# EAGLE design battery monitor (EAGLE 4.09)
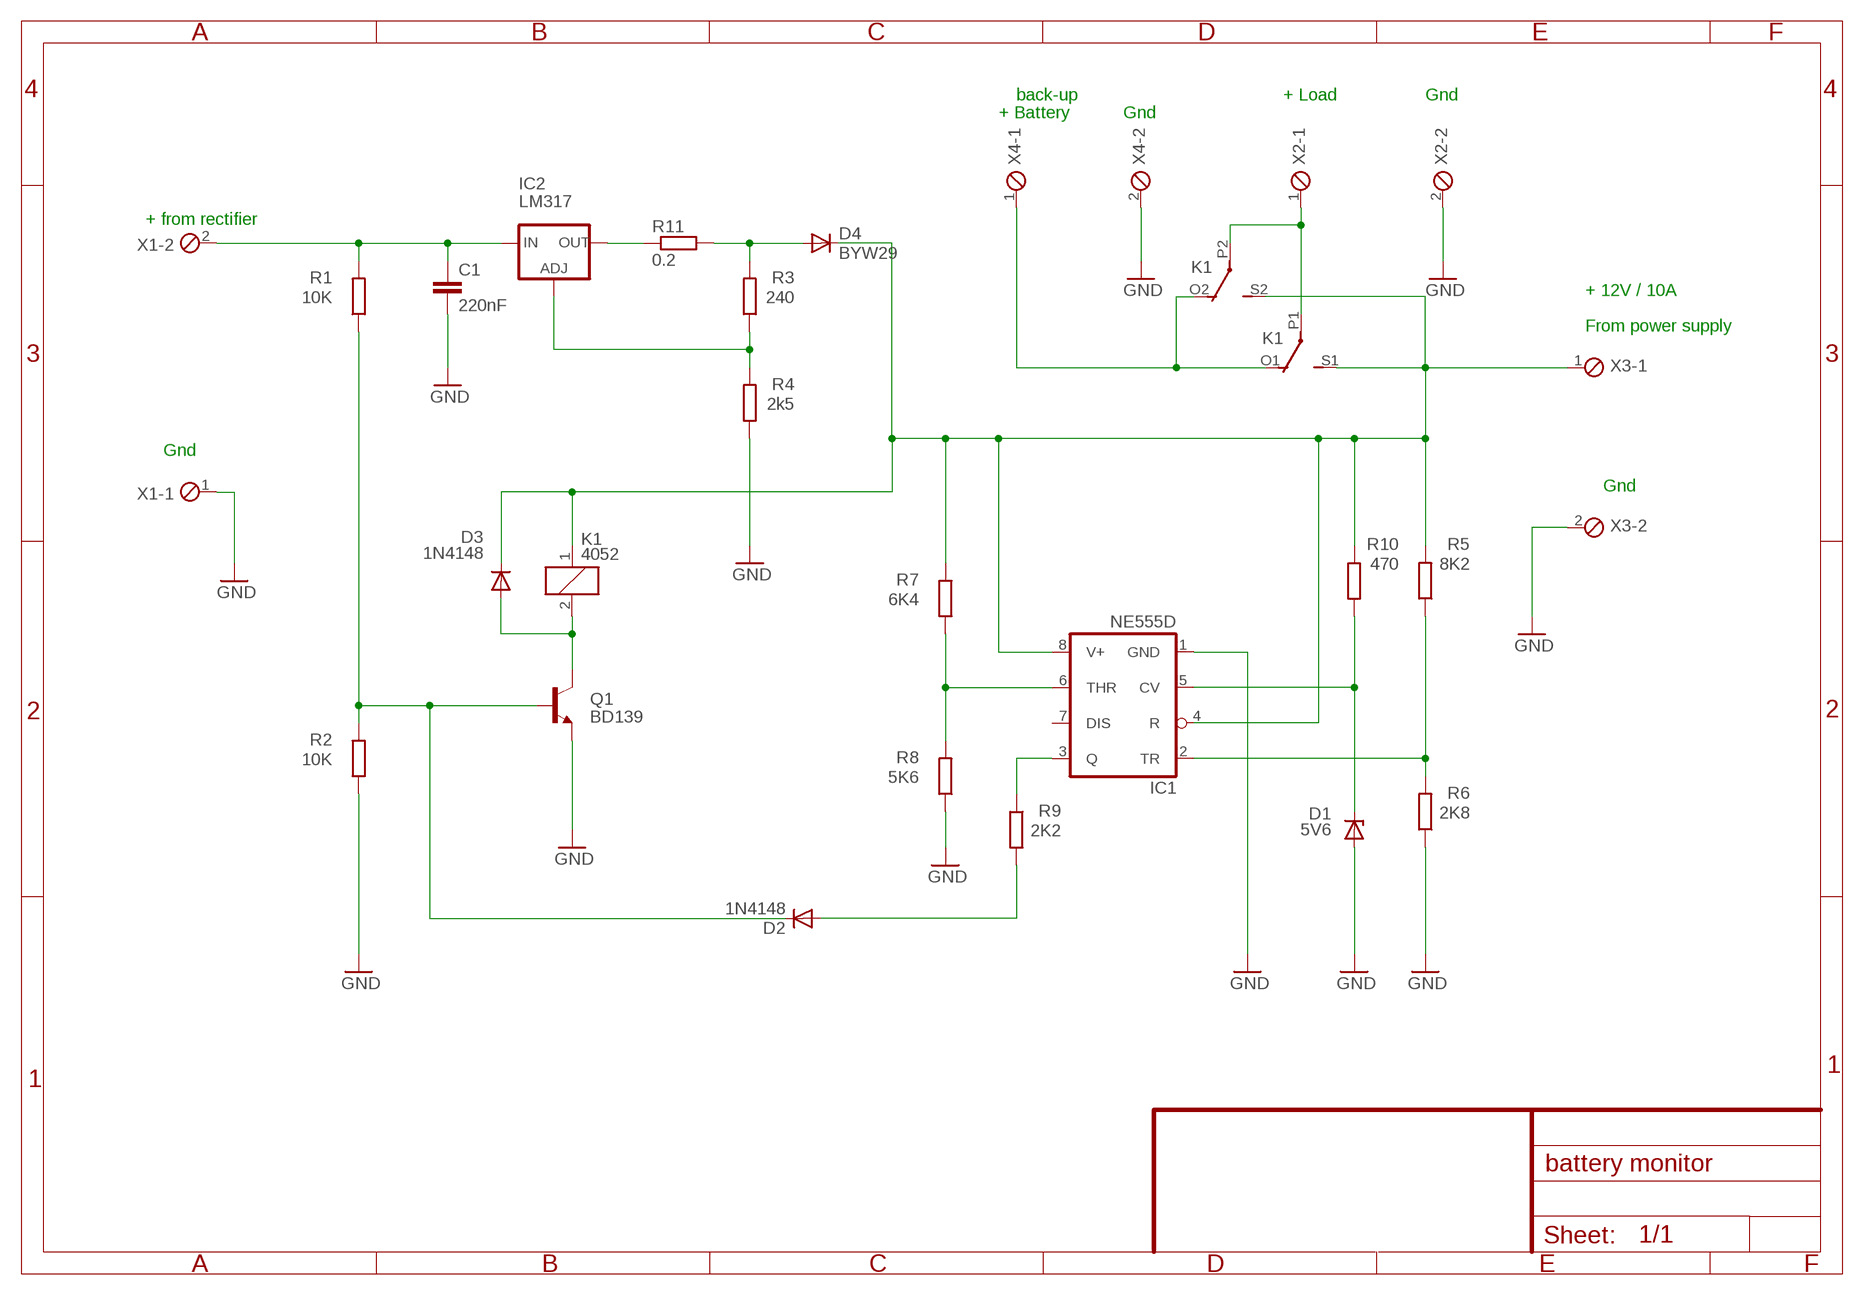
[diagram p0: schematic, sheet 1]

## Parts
C1  220nF  C-EU025_050-035X075  [C025_050-035X075]
D1  5V6  ZENER-DIODESMB  [SMB]
D2  1N4148  DIODE-SMB  [SMB]
D3  1N4148  DIODE-SMB  [SMB]
D4  BYW29  [DO220S]
IC1  NE555D  [SO08]
IC2  LM317  LM317TS  [317TS]
K1  4052  [F4052]
Q1  BD139  [TO126]
R1  10K  R-EU_M1206  [M1206]
R2  10K  R-EU_M1206  [M1206]
R3  240  R-EU_M1206  [M1206]
R4  2k5  R-EU_M1206  [M1206]
R5  8K2  R-EU_M1206  [M1206]
R6  2K8  R-EU_M1206  [M1206]
R7  6K4  R-EU_M1206  [M1206]
R8  5K6  R-EU_M1206  [M1206]
R9  2K2  R-EU_M1206  [M1206]
R10  470  R-EU_M1206  [M1206]
R11  0.2  R-EU_0922/22  [0922/22]
X1  MPT2  [2POL254]
X2  MPT2  [2POL254]
X3  MPT2  [2POL254]
X4  MPT2  [2POL254]

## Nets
GND: C1.2 D1.A IC1.1(GND) Q1.1(E) R2.1 R4.1 R6.1 R8.1 X1.1 X2.2 X3.2 X4.2
N$1: IC1.6(THR) R7.1 R8.2
N$2: IC1.2(TR) R5.1 R6.2
N$3: IC1.3(Q) R9.1
N$4: D2.A R9.2
N$5: D1.C IC1.5(CV) R10.2
N$6: C1.1 IC2.3(IN) R1.2 X1.2
N$7: IC2.2(OUT) R11.1
N$8: D4.A R3.2 R11.2
N$9: IC2.1(ADJ) R3.1 R4.2
N$10: D3.A K1.2 Q1.2(C)
N$11: D2.C Q1.3(B) R1.1 R2.2
N$12: K1.P1(2:P) K1.P2(3:P) X2.1
N$13: D3.C D4.C IC1.4(R) IC1.8(V+) K1.1 K1.S1(2:S) K1.S2(3:S) R5.2 R7.2 R10.1 X3.1
N$14: K1.O1(2:O) K1.O2(3:O) X4.1
Unconnected: IC1.7(DIS)

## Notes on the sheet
- back-up | + Load | Gnd
- + Battery | Gnd
- + from rectifier
- + 12V / 10A
- From power supply
- Gnd
- Gnd

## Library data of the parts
C1 = rcl:C-EU: CAPACITOR, European symbol
D1 = diode:ZENER-DIODE: Z-Diode
D2 D3 = diode:DIODE-: DIODE
D4 = diode:BYW29: DIODE
IC1 = linear:*555: TIMER
IC2 = v-reg:LM317TS: VOLTAGE REGULATOR
K1 = relay:4052: RELAY 2 x switch, Finder
Q1 = transistor-npn:BD139*: NPN Transistor
R1-R11 = rcl:R-EU_: RESISTOR, European symbol
X1-X4 = con-phoenix-254:MPT2: PHOENIX CONNECTOR

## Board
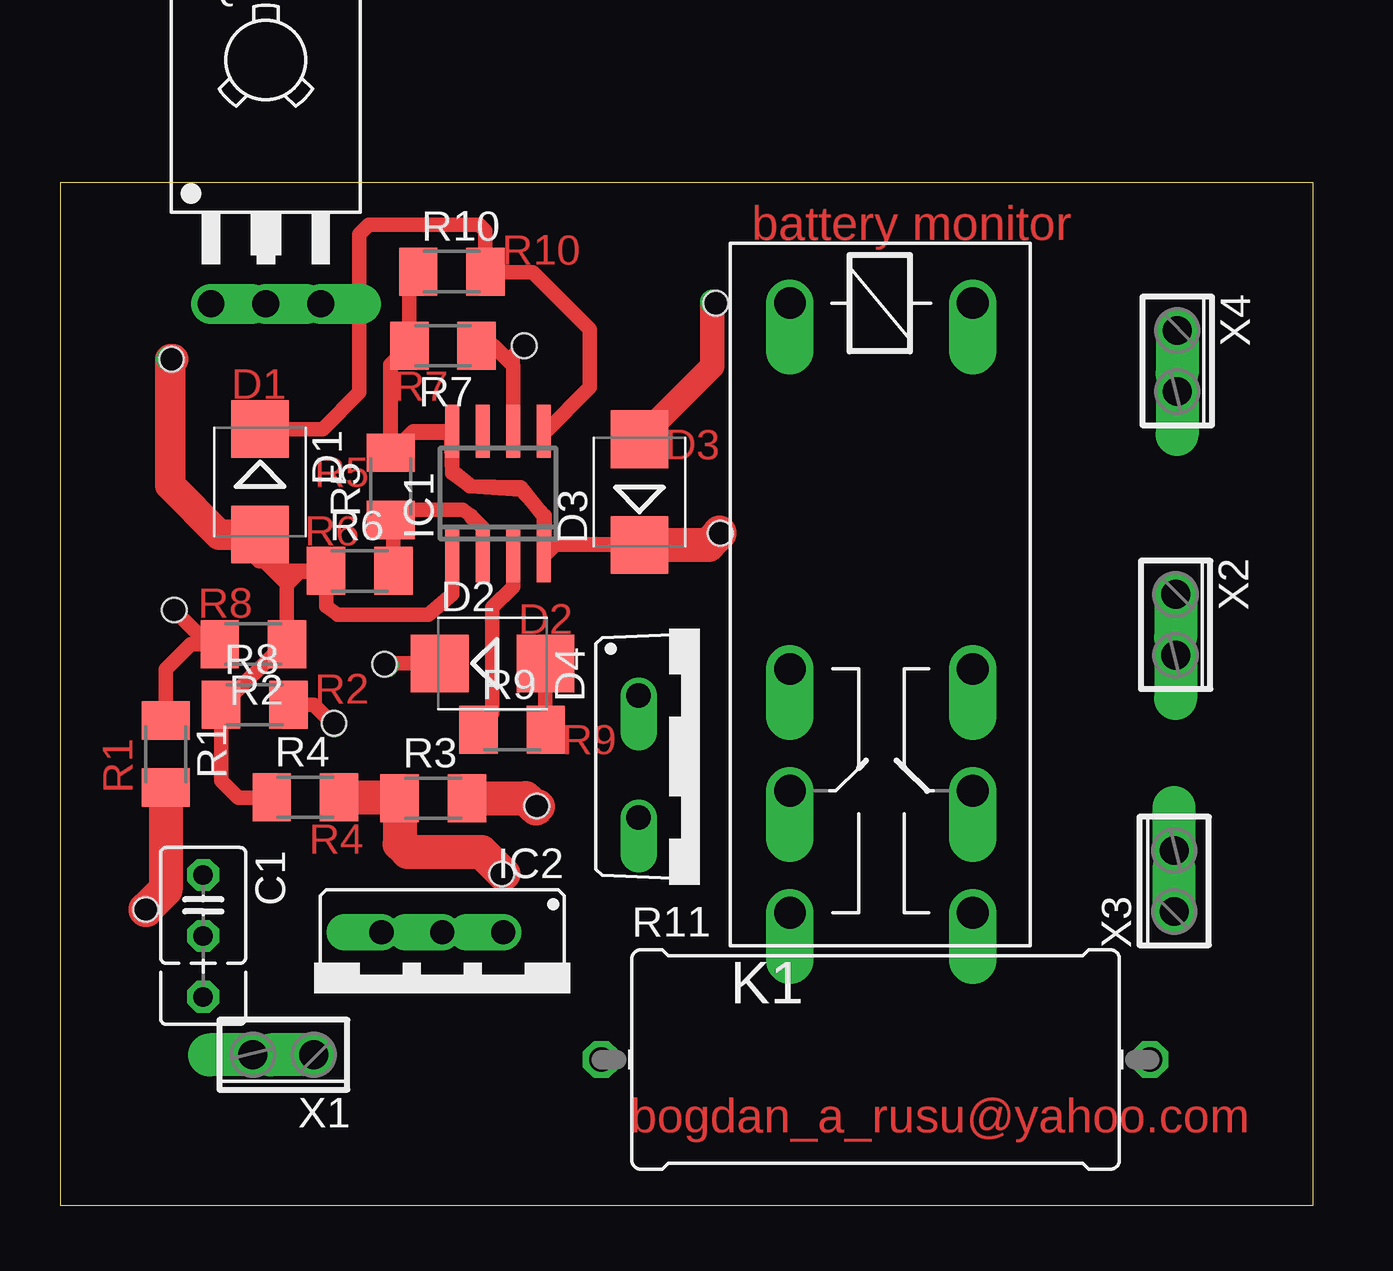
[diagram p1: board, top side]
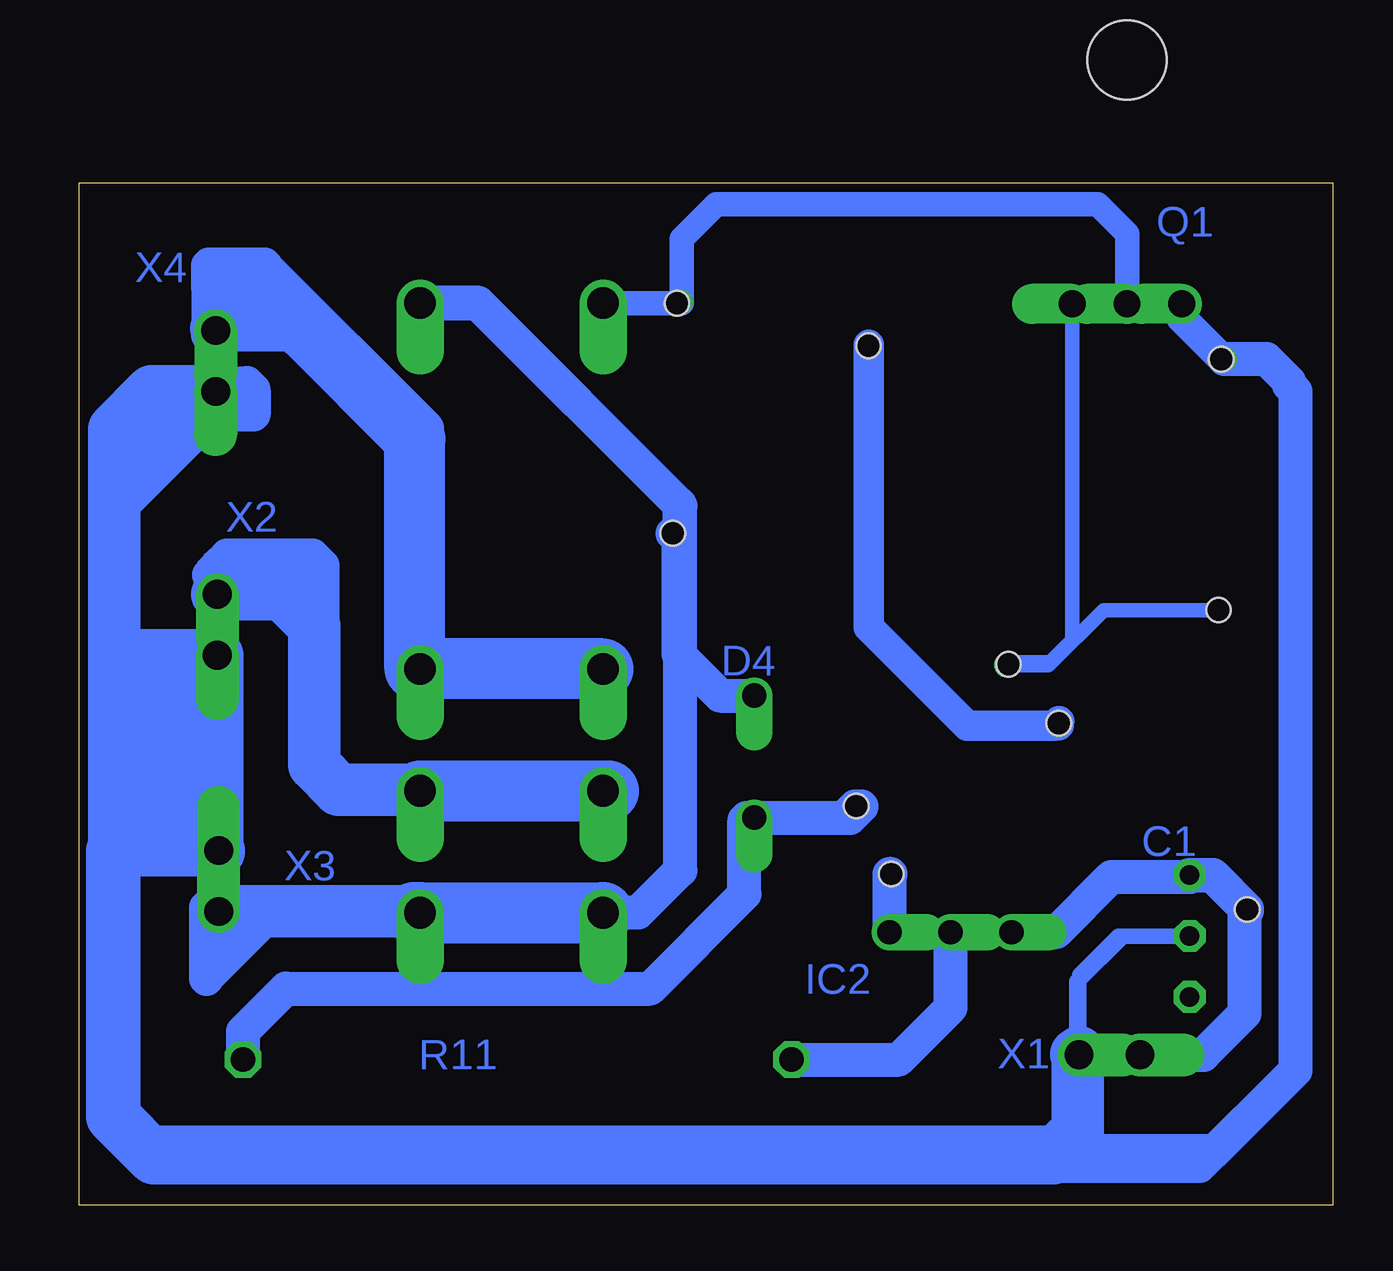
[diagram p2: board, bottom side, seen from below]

Size 52.23 x 42.62 mm. Coordinates in mm from the lower left corner, seen from the top.
Outline: 0,0 52.23,0 52.23,42.62 0,42.62 0,0
Copper layers used: Top, Bottom
Holes 1.02 mm at 19.86,16.64 18.4,13.8 3.57,12.33 27.51,28 27.33,37.59 4.65,35.25 13.52,22.55 4.76,24.81 19.35,35.82 11.42,20.09

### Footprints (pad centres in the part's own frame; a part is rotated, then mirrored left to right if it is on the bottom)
C025_050-035X075 = drill 0.813 octagon: 1 -1.27,0; 2 1.27,0; 3 3.81,0
SMB = smd 2.4 x 2.4: A 2.2,0; C -2.2,0
DO220S = drill 1.016 offset: A 2.54,-2.54; C -2.54,-2.54
SO08 = smd 0.6 x 2.2: 1 -1.905,-2.6; 2 -0.635,-2.6; 3 0.635,-2.6; 4 1.905,-2.6; 5 1.905,2.6; 6 0.635,2.6; 7 -0.635,2.6; 8 -1.905,2.6
317TS = drill 1.016 offset: 1 -2.54,-2.54; 2 0,-2.54; 3 2.54,-2.54
F4052 = drill 1.321 offset: 1 -3.81,3.81; 2 -3.81,-3.81; O1 11.43,-3.81; O2 11.43,3.81; P1 16.51,-3.81; P2 16.51,3.81; S1 21.59,-3.81; S2 21.59,3.81
TO126 = drill 1.118 offset: 1 -2.286,-5.08; 2 0,-5.08; 3 2.286,-5.08 | hole 3.302: 0,5.08
M1206 = smd 1.6 x 2: 1 -1.4,0; 2 1.4,0
0922/22 = drill 1.016 octagon: 1 -11.43,0; 2 11.43,0
2POL254 = drill 1.2 offset: 1 -1.27,0; 2 1.27,0

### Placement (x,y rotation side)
C1  5.97,12.5 270 top
D1  8.33,30.15 270 top
D2  18.02,22.58 0 top
D3  24.14,29.72 90 top
D4  26.65,18.7 270 top
IC1  18.25,29.66 0 top
IC2  15.93,8.84 180 top
K1  34.22,33.78 270 top
Q1  8.58,42.64 0 top
R1  4.4,18.8 270 top
R2  8.06,23.39 180 top
R3  15.55,16.96 0 top
R4  10.22,17.01 0 top
R5  13.78,29.96 90 top
R6  12.49,26.43 0 top
R7  15.96,35.82 180 top
R8  8.11,20.86 0 top
R9  18.84,19.81 0 top
R10  16.33,38.91 0 top
R11  33.98,6.08 0 top
X1  9.31,6.28 180 top
X2  46.48,24.19 270 top
X3  46.42,13.52 90 top
X4  46.55,35.18 270 top

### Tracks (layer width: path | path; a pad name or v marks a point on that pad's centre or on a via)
GND  (via drill 0.61)
  Top 0.406: R4.1 7.52,17.01 6.62,17.91 6.62,20.95 6.68,21.02 6.96,21.02 9.39,23.45 9.39,25.81 8.44,26.76 8.24,26.76 6.01,28.98 5.87,28.98 4.46,30.4 4.46,35.2 v4.52,35.26
  Top 0.61: R4.1 8.78,17.01 8.76,16.99 7.42,16.99 6.71,17.7 R8.1 6.79,20.86 9.31,23.39 R2.1 9.46,25.86 10,26.4 10.94,26.4 10.97,26.43 R6.1 | R6.1 9.12,26.43 8.32,27.24 8.32,27.89 8.27,27.93 8.28,27.95 D1.A | R6.1 11.09,26.4 11.04,26.35 11.09,26.3 11.09,24.96 11.58,24.62 15.35,24.62 16.35,25.47 16.35,25.49 16.34,25.5 16.35,25.51 IC1.1
  Top 1.27: D1.A 6.64,27.95 4.59,30 4.59,35.13 4.73,35.26 v4.59,35.26
  Bottom 0.61: 10.56,6.37 10.56,9.61 8.94,11.23 C1.2 5.97,11.24 | 10.7,6.31 10.7,9.34 8.84,11.2 | 5.97,11.24 5.95,11.26 | 8.84,11.2 6.01,11.2 5.97,11.24 | 8.74,11.2 8.71,11.23 | 8.74,11.2 8.84,11.2 | 10.67,2.92 10.67,9.27 8.74,11.2
  Bottom 1.27: Q1.1 6.29,36.97 v4.59,35.26
  Bottom 1.422: v4.52,35.26 2.77,35.26 1.82,34.32 1.82,34.18 1.55,33.91 1.55,5.62 4.93,2.24 9.99,2.24 10.67,2.92
  Bottom 2.184: X4.2 49.21,33.91 50.78,32.34 50.78,22.9 | 50.78,22.9 50.78,3.69 49.06,1.97 11.8,1.97 10.63,3.14 10.63,6.31 10.56,6.37 | 50.78,22.9 50.77,22.92 X2.2 46.48,14.75 46.45,14.71 46.42,14.73 X3.2 50.84,14.79 50.85,14.78 50.85,3.69 49.13,1.97 11.66,1.97 10.63,3 | 50.78,22.9 50.78,3.62 49.41,2.24 11.39,2.24 10.63,3 | X1.1 10.58,6.11 10.56,6.1 10.63,6.03 10.63,3 | 10.63,3 10.63,6.24 10.7,6.31
N$1  (via drill 0.61)
  Top 0.61: IC1.6 18.89,34.99 18.12,35.76 17.33,35.76 17.36,35.79 R7.1 18.08,35.82 18.87,35.03 18.87,35.39 v19.35,35.86 | R8.2 10.57,20.86 v11.42,20.01
  Bottom 1.27: v19.35,35.86 19.35,24.09 15.25,19.99 11.59,19.99 11.42,20.16 | 11.41,20.18 11.42,20.16 | 11.42,20.16 v11.42,20.01
N$2
  Top 0.61: IC1.2 17.62,28.24 17.23,28.63 17.18,28.63 17.13,28.68 17.13,28.73 16.78,28.97 13.81,28.97 13.78,28.74 R5.1 13.69,28.56 13.66,28.53 13.89,28.3 R6.2
N$3
  Top 0.61: IC1.3 18.89,25.78 18.02,24.91 18.02,20.51 17.33,19.81 | 17.28,19.76 17.33,19.81 | 17.33,19.81 R9.1
N$4
  Top 0.61: 20.22,19.54 20.24,19.56 R9.2 | D2.A 20.22,19.54 | 20.22,19.54 20.2,19.52
N$5
  Top 0.61: D1.C 10.94,32.35 12.47,33.88 12.47,40.47 12.87,40.86 17.47,40.86 17.72,40.61 17.72,38.93 17.67,38.88 | 17.67,38.88 17.7,38.91 R10.2 | 17.67,38.88 19.7,38.88 22.08,36.5 22.08,34.08 20.22,32.22 20.17,32.26 IC1.5
N$6  (via drill 0.61)
  Top 1.422: v3.57,12.35 4.4,13.18 R1.2 4.4,13.14 v3.57,12.31 v3.61,12.31
  Bottom 1.422: X1.2 5.4,6.27 3.67,8 3.67,12.24 v3.61,12.31 | C1.1 4.99,13.77 v3.57,12.35 | IC2.3 11.54,11.38 9.23,13.69 5.95,13.69 5.88,13.76 5.05,13.76 3.57,12.28 v3.57,12.31
N$7
  Bottom 1.422: R11.1 18.09,6.08 15.93,8.23 15.93,11.2 16.07,11.33 16.02,11.38 IC2.2
N$8  (via drill 0.61)
  Top 0.61: 19.95,16.54 19.92,16.58 | 19.92,16.58 v19.92,16.62 | R3.2 19.53,16.96 19.92,16.58
  Top 1.422: v19.92,16.62 19.83,16.53 19.4,16.96 R3.2 | v19.92,16.62
  Bottom 1.422: D4.A 20.37,16.16 v19.92,16.62 19.65,16.62 | R11.2 45.41,7.24 43.63,9.03 28.45,9.03 24.52,12.96 24.52,16.05 24.43,16.15 20.12,16.15 19.65,16.62 | 19.65,16.62
N$9  (via drill 0.61)
  Top 1.422: R4.2 14.08,17.01 14.12,16.96 R3.1 14.15,15.06 14.48,14.73 17.56,14.73 v18.47,13.81
  Bottom 1.422: v18.47,13.81 18.43,13.81 18.47,13.77 IC2.1
N$10  (via drill 0.61)
  Top 1.016: D3.A 27.18,34.96 v27.18,37.64
  Bottom 1.016: v27.18,37.64 27.23,37.59 K1.2 30.45,37.59 | Q1.2 8.58,40.48 9.8,41.7 25.69,41.7 27.13,40.27 27.13,37.59 30.45,37.59 | 30.5,37.64 30.45,37.59
N$11  (via drill 0.61)
  Top 0.61: R1.1 4.4,22.34 5.44,23.38 6.48,23.38 6.63,23.23 6.66,23.26 R2.2 6.18,23.39 v4.76,24.81 | 13.48,22.51 13.55,22.58 D2.C 13.47,22.58 13.44,22.55 13.48,22.51 | 13.48,22.51 v13.6,22.51
  Bottom 0.61: v4.76,24.81 9.56,24.81 11.86,22.51 v13.6,22.51 | v13.6,22.51 13.64,22.51 | Q1.3 10.87,23.54 11.78,22.63 13.48,22.63 v13.6,22.51
N$12
  Bottom 2.184: X2.1 43.76,25.46 42.45,24.14 42.45,18.36 41.42,17.33 30.47,17.33 K1.P1
  Bottom 2.54: K1.P2 K1.P1 30.21,17.27 30.19,17.26
N$13  (via drill 0.61)
  Top 0.61: IC1.4 20.15,27.04 | IC1.4 20.16,28.72 19.21,29.92 17.13,29.97 16.34,30.61 16.34,32.14 16.35,32.15 IC1.8 14.72,32.26 13.78,31.32 | D3.C 20.63,27.52 IC1.4 | 13.78,31.32 13.76,31.3 | 13.78,31.32 R5.2 13.78,35.03 R7.2 14.56,38.54 R10.1 14.93,38.46 14.55,38.09 R7.2 13.76,35.02 13.76,31.3 | 13.76,31.3 13.76,31.25 | 13.76,31.3 14.65,32.19 16.29,32.19 16.34,30.51 17.08,29.97 19.21,29.82 20.2,28.73 20.2,27.64 20.3,27.54 26.98,27.54 27.52,28.08 v27.52,27.98
  Top 1.422: v27.48,28.03 27.48,27.98 27.01,27.52 D3.C
  Bottom 1.422: K1.S2 28.96,12.19 27.19,13.96 27.19,29.15 35.66,37.62 38.07,37.62 K1.1 35.6,37.59 27.23,29.22 27.23,28.28 v27.52,27.98 | D4.C 25.53,21.24 27.28,22.98 27.28,27.84 v27.48,28.03
  Bottom 2.184: K1.S1 30.41,12.21 30.4,12.23 30.42,12.25 X3.1
  Bottom 2.54: K1.S1 K1.S2 38.28,12.19 38.32,12.16
N$14
  Bottom 1.93: X4.1 46.56,36.45 46.65,36.54 42.86,36.54 | 38.04,22.28 38.03,22.3 | 38.03,22.3 K1.O2 | K1.O1 37.97,22.35 38.03,22.3
  Bottom 2.54: K1.O1 K1.O2 38.25,22.35 38.25,31.93 42.86,36.54
N$15  (via drill 0.61)
  other vias: 19.86,16.64
N$16  (via drill 0.61)
  other vias: 18.41,13.8
N$17  (via drill 0.61)
  other vias: 3.57,12.31
N$18  (via drill 0.61)
  other vias: 27.51,27.99
N$19  (via drill 0.61)
  other vias: 27.33,37.59
N$20  (via drill 0.61)
  other vias: 4.65,35.25
N$21  (via drill 0.61)
  other vias: 13.52,22.55
N$22  (via drill 0.61)
  other vias: 4.76,24.81
N$23  (via drill 0.61)
  other vias: 19.35,35.82
N$24  (via drill 0.61)
  other vias: 11.42,20.09
N$25
  Bottom 1.422: 14.16,1.64 5.55,1.64 1.57,5.62
N$26
  Bottom 1.422: 42.78,37.06 46.39,37.06 46.73,36.73
N$27
  Bottom 1.422: 47.6,21.74 47.6,16 47.7,15.9 49.08,15.9 49.12,15.87 49.12,21.85 49.29,22.02 48.36,22.02 48.36,17.01 48.15,16.8
N$28
  Bottom 1.422: 42.1,23.58 42.1,26.65 42.51,27.07 46.07,27.07 46.14,27 46.14,26.86 46.56,26.45 46.56,26.58 46.39,26.76 46.39,26.72 46.84,26.27 43.17,26.27 43.07,26.17
N$29
  Bottom 1.422: 46.77,34.26 45.25,34.26 44.97,33.98 44.97,32.95 46.63,32.95 | 46.63,32.95 49.12,32.95 49.12,32.81 50.5,31.43 50.5,30.8 50.47,30.77 50.47,30.84 48.43,32.88 46.7,32.88 46.63,32.95 | 46.63,32.95 | 46.63,32.95 50.26,29.32
N$30
  Bottom 1.422: 42.31,36.72 | 42.31,36.72 43.93,38.34 46.8,38.34 46.87,38.27 | 46.87,38.27 46.87,36.27 | 46.87,38.27 46.87,39.17 46.84,39.21 44.52,39.21 44.48,39.17 44.48,39.14 37.74,32.39
N$31
  Bottom 1.422: 46.96,12.41 46.96,9.46 46.93,9.43 46.93,9.49 44.47,11.95

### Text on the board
Top: battery monitor | R10 | D1 | R7 | D3 | R5 | R6 | R8 | D2 | R2 | R9 | R1 | R4 | bogdan_a_rusu@yahoo.com
Bottom: Q1 | X4 | X2 | D4 | C1 | X3 | IC2 | X1 | R11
